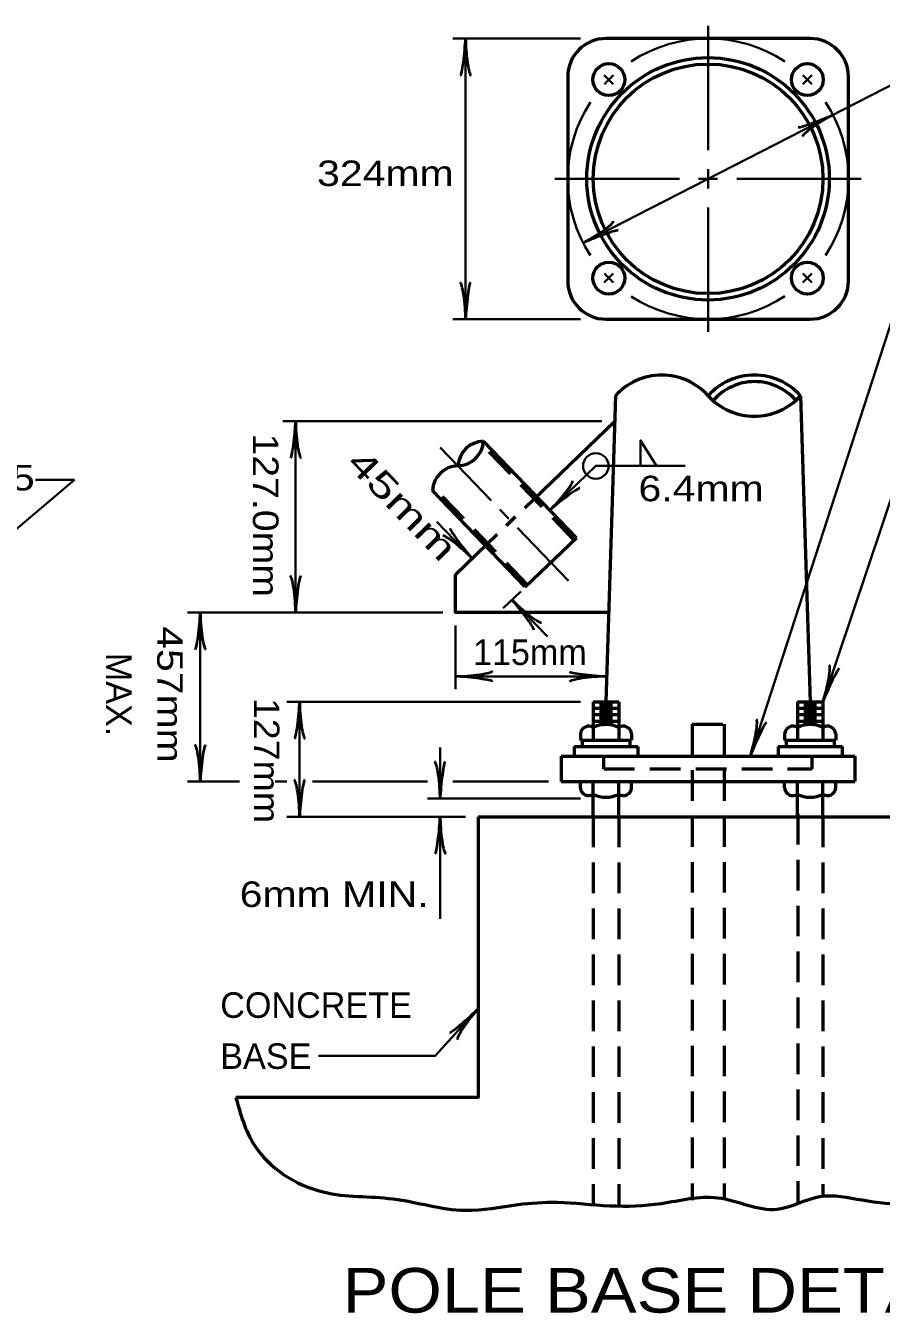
# Model space of a CAD drawing. Extents: x -35 to 821, y -13 to 531.
# Drawn here: x 258.8 to 339.2, y 119.8 to 240.9 of the extents above; entities that cross this region are included whole.
import ezdxf
from ezdxf.enums import TextEntityAlignment as Align

# ---------------------------------------------------------------- set-up
doc = ezdxf.new("R2010")
doc.units = 0
doc.header["$LTSCALE"] = 0.96
doc.linetypes.add('MEDIUM_DASHED', pattern=[4.5, 3, -1.5])
doc.layers.add('1', color=7, linetype='Continuous', lineweight=53)

msp = doc.modelspace()

# ---------------------------------------------------------------- linework, layer by layer
at = {"layer": '1', "lineweight": 35}
for p, q in [((322.9347, 240.8878), (322.9347, 229.1878)), ((310.9347, 239.6878), (298.9347, 239.6878)), ((300.1347, 239.6878), (300.1347, 213.2878)), ((342.1524, 236.3488), (311.1905, 220.4616)), ((313.1766, 236.2458), (314.025, 235.3974)), ((332.6927, 236.2458), (331.8443, 235.3974)), ((308.5347, 226.4878), (320.2347, 226.4878)), ((325.6347, 226.4878), (337.3347, 226.4878)), ((322.9347, 223.7878), (322.9347, 212.0878)), ((314.0251, 217.5782), (313.1767, 216.7298)), ((331.8442, 217.5782), (332.6927, 216.7298)), ((310.9347, 213.2878), (298.9347, 213.2878)), ((333.7347, 177.2878), (343.3335, 205.9941)), ((312.9597, 203.6887), (282.9597, 203.6887)), ((284.1597, 203.6887), (284.1597, 185.6837)), ((299.4156, 199.4884), (297.751, 201.2173)), ((302.5365, 196.2466), (299.4155, 199.4884)), ((225.8081, 166.5182), (263.3752, 198.1859)), ((259.6859, 198.1859), (263.3752, 198.1859)), ((304.2011, 194.5177), (303.3688, 195.3822)), ((300.7525, 190.7812), (297.4234, 194.239)), ((309.8189, 188.6825), (305.0333, 193.6532)), ((303.6759, 186.0998), (305.3196, 187.6823)), ((307.8269, 183.4332), (304.4978, 186.8911)), ((297.997, 185.6837), (273.997, 185.6837)), ((275.197, 185.6837), (275.197, 169.7878)), ((299.197, 184.4837), (299.197, 178.4837)), ((299.197, 179.6837), (313.372, 179.6837)), ((310.9347, 177.2878), (283.3347, 177.2878)), ((284.5347, 177.2878), (284.5347, 166.4878)), ((297.7458, 168.1914), (297.7458, 172.9914)), ((278.8687, 169.7878), (273.997, 169.7878)), ((283.3347, 169.7878), (282.2422, 169.7878)), ((296.5458, 169.7878), (285.7347, 169.7878)), ((307.9347, 169.7878), (298.9458, 169.7878)), ((310.9458, 168.1914), (296.5458, 168.1914)), ((300.1347, 166.4878), (283.3347, 166.4878)), ((297.7458, 166.4878), (297.7458, 156.8878))]:
    msp.add_line(p, q, dxfattribs=at)
at = {"layer": '1'}
for p, q in [((332.5347, 239.6878), (313.3347, 239.6878)), ((309.7347, 236.0878), (309.7347, 216.8878)), ((336.1347, 216.8878), (336.1347, 236.0878)), ((313.3347, 213.2878), (332.5347, 213.2878)), ((314.2347, 206.0878), (313.3346, 177.2878)), ((331.6347, 206.0878), (332.5347, 177.2878)), ((305.7058, 195.5498), (314.1597, 203.6887)), ((310.5569, 192.7245), (301.8181, 201.8014)), ((305.7518, 188.0984), (297.0128, 197.1752)), ((303.9769, 193.8854), (304.8414, 194.7176)), ((299.197, 189.2837), (303.1124, 193.0531)), ((305.7518, 188.0984), (310.5569, 192.7245)), ((312.1347, 177.2878), (314.5347, 177.2878)), ((312.1347, 177.2878), (312.1347, 174.8878)), ((312.7347, 176.9878), (313.9347, 176.9878)), ((314.5347, 177.2878), (314.5347, 174.8878)), ((331.3347, 177.2878), (333.7347, 177.2878)), ((331.3347, 177.2878), (331.3347, 174.8878)), ((331.9347, 176.9878), (333.1347, 176.9878)), ((333.7347, 177.2878), (333.7347, 174.8878)), ((312.1347, 176.6878), (314.5347, 176.6878)), ((312.1347, 176.0878), (314.5347, 176.0878)), ((312.7347, 176.3878), (313.9347, 176.3878)), ((312.7347, 175.7878), (313.9347, 175.7878)), ((331.3347, 176.6878), (333.7347, 176.6878)), ((331.3347, 176.0878), (333.7347, 176.0878)), ((331.9347, 176.3878), (333.1347, 176.3878)), ((331.9347, 175.7878), (333.1347, 175.7878)), ((312.1347, 175.4878), (314.5347, 175.4878)), ((312.1347, 174.8878), (312.1347, 173.6878)), ((312.7347, 175.1878), (313.9347, 175.1878)), ((314.5347, 174.8878), (314.5347, 173.6878)), ((331.3347, 175.4878), (333.7347, 175.4878)), ((331.3347, 174.8878), (331.3347, 173.6878)), ((331.9347, 175.1878), (333.1347, 175.1878)), ((333.7347, 174.8878), (333.7347, 173.6878)), ((310.9347, 174.2878), (310.9347, 173.6878)), ((310.9347, 173.6878), (315.7347, 173.6878)), ((311.0847, 173.6878), (311.0847, 173.0878)), ((315.5847, 173.6878), (315.5847, 173.0878)), ((315.7347, 174.2878), (315.7347, 173.6878)), ((330.1347, 174.2878), (330.1347, 173.6878)), ((330.1347, 173.6878), (334.9347, 173.6878)), ((330.2847, 173.6878), (330.2847, 173.0878)), ((334.7847, 173.6878), (334.7847, 173.0878)), ((334.9347, 174.2878), (334.9347, 173.6878)), ((309.1347, 172.1878), (336.7347, 172.1878)), ((309.1347, 172.1878), (309.1347, 169.7878)), ((310.3347, 173.0878), (316.3347, 173.0878)), ((310.3347, 173.0878), (310.3347, 172.1878)), ((316.3347, 173.0878), (316.3347, 172.1878)), ((329.5347, 173.0878), (335.5347, 173.0878)), ((329.5347, 173.0878), (329.5347, 172.1878)), ((335.5347, 173.0878), (335.5347, 172.1878)), ((336.7347, 172.1878), (336.7347, 169.7878)), ((309.1347, 169.7878), (336.7347, 169.7878)), ((310.9347, 169.1878), (310.9347, 169.7878)), ((312.1347, 166.4878), (312.1347, 169.7878)), ((314.5347, 166.4878), (314.5347, 169.7878)), ((315.7347, 169.1878), (315.7347, 169.7878)), ((330.1347, 169.1878), (330.1347, 169.7878)), ((331.3347, 166.4878), (331.3347, 169.7878)), ((333.7347, 166.4878), (333.7347, 169.7878)), ((334.9347, 169.1878), (334.9347, 169.7878))]:
    msp.add_line(p, q, dxfattribs=at)
at = {"layer": '1', "linetype": 'MEDIUM_DASHED'}
for p, q in [((310.3406, 192.5162), (301.7641, 201.4245)), ((305.9678, 188.3064), (297.0667, 197.5516)), ((321.4347, 175.1878), (321.4347, 130.4043)), ((321.4347, 175.1878), (324.4347, 175.1878)), ((324.4347, 175.1878), (324.4347, 130.6498)), ((313.1378, 170.9878), (313.1378, 172.1878)), ((332.7316, 170.9878), (332.7316, 172.1878)), ((313.1378, 170.9878), (332.7316, 170.9878)), ((312.1347, 166.4878), (312.1347, 129.973)), ((314.5347, 166.4878), (314.5347, 129.913)), ((331.359, 166.7575), (331.359, 130.1869)), ((333.7347, 166.4878), (333.7347, 130.7353))]:
    msp.add_line(p, q, dxfattribs=at)
at = {"layer": '1', "lineweight": 35}
for points in [[(322.0347, 226.4878), (322.9347, 226.4878), (323.8347, 226.4878)], [(322.9347, 227.3878), (322.9347, 226.4878), (322.9347, 225.5878)], [(326.909, 172.1878), (342.9245, 221.5527), (344.2093, 221.5527)], [(316.5825, 199.4791), (316.5825, 201.8791), (318.0825, 199.4791)], [(308.0602, 195.3178), (312.3825, 199.4791), (320.7825, 199.4791)], [(301.3347, 148.4451), (297.2801, 143.9966), (286.2943, 143.9966)]]:
    msp.add_lwpolyline(points, dxfattribs=at)
at = {"layer": '1'}
for points in [[(313.597, 185.6837), (299.197, 185.6837), (299.197, 189.2837)], [(301.3347, 166.4878), (301.3347, 140.0878), (278.5347, 140.0878)], [(301.3347, 166.4878), (344.5347, 166.4878), (344.5347, 130.4878)]]:
    msp.add_lwpolyline(points, dxfattribs=at)
for centre, radius in [((322.9347, 226.4878), 11.4), ((313.6009, 235.8216), 1.5), ((322.9347, 226.4878), 10.8), ((332.2685, 235.8216), 1.5), ((313.6009, 217.154), 1.5), ((332.2685, 217.154), 1.5)]:
    msp.add_circle(centre, radius, dxfattribs=at)
at = {"layer": '1', "lineweight": 35}
msp.add_circle((312.3825, 199.4791), 1.2, dxfattribs=at)
at = {"layer": '1'}
for centre, radius, start, end in [((313.3347, 236.0878), 3.6, 90, 180), ((332.5347, 236.0878), 3.6, 0, 90), ((313.3347, 216.8878), 3.6, 180, 270), ((332.5347, 216.8878), 3.6, 270, 0), ((318.5847, 202.1523), 5.8661, 42.13622, 137.86423), ((327.2847, 202.1523), 5.8661, 42.13622, 137.86378), ((327.3185, 202.2532), 5.1594, 41.23283, 139.26556), ((327.2847, 210.0233), 5.8661, 222.13622, 317.86378), ((301.8862, 199.3265), 2.476, 91.57437, 176.25114), ((299.3475, 201.9635), 2.476, 271.57437, 356.25114), ((299.4835, 197.0133), 2.476, 91.57437, 176.25114), ((311.7162, 174.2249), 0.784, 57.73362, 175.39648), ((313.3347, 172.3871), 2.7738, 64.36559, 115.6344), ((314.9532, 174.2249), 0.784, 4.60352, 122.26638), ((330.9162, 174.2249), 0.784, 57.73362, 175.39648), ((332.5347, 172.3871), 2.7738, 64.36559, 115.6344), ((334.1532, 174.2249), 0.784, 4.60352, 122.26638), ((311.7162, 169.2507), 0.784, 184.60352, 302.26638), ((313.3347, 171.0885), 2.7738, 244.3656, 295.63441), ((314.9532, 169.2507), 0.784, 237.73362, 355.39648), ((330.9162, 169.2507), 0.784, 184.60352, 302.26638), ((332.5347, 171.0885), 2.7738, 244.3656, 295.63441), ((334.1532, 169.2507), 0.784, 237.73362, 355.39648)]:
    msp.add_arc(centre, radius, start, end, dxfattribs=at)
at = {"layer": '1', "lineweight": 35}
for start, end in [(56.77694, 123.15721), (132.39545, 137.60578), (42.39484, 47.60516), (146.85345, 213.14435), (326.86294, 33.16035), (222.39484, 227.60516), (312.39437, 317.6047), (236.86662, 303.17329)]:
    msp.add_arc((322.9347, 226.4878), 13.2, start, end, dxfattribs=at)
at = {"layer": '1', "lineweight": 40}
for centre, major_axis, ratio, start_param, end_param in [((299.8808, 238.3432), (0.2108, 2.1077), 0.07063, 3.14071475, 5.41810995), ((299.8808, 238.3432), (0.2108, 2.1077), 0.07063, 3.14071475, 5.41810995), ((300.4663, 238.3784), (-0.1874, 2.1428), 0.122415, 0.89635335, 3.14159265), ((300.4663, 238.3784), (-0.1874, 2.1428), 0.122415, 0.89635335, 3.14159265), ((333.3667, 232.1261), (1.9715, 0.7747), 0.07063, 3.14071475, 5.41810995), ((333.3667, 232.1261), (1.9715, 0.7747), 0.07063, 3.14071475, 5.41810995), ((333.6652, 231.6212), (1.821, 1.145), 0.122415, 0.89635335, 3.14159265), ((333.6652, 231.6212), (1.821, 1.145), 0.122415, 0.89635335, 3.14159265), ((312.2042, 221.3544), (-1.821, -1.145), 0.122415, 0.89635335, 3.14159265), ((312.5027, 220.8495), (-1.9715, -0.7747), 0.07063, 3.14071475, 5.41810995), ((299.8031, 214.5972), (0.1874, -2.1428), 0.122415, 0.89635335, 3.14159265), ((300.3886, 214.6324), (-0.2108, -2.1077), 0.07063, 3.14071475, 5.41810995), ((283.9058, 202.3441), (0.2108, 2.1077), 0.07063, 3.14071475, 5.41810995), ((283.9058, 202.3441), (0.2108, 2.1077), 0.07063, 3.14071475, 5.41810995), ((284.4913, 202.3793), (-0.1874, 2.1428), 0.122415, 0.89635335, 3.14159265), ((284.4913, 202.3793), (-0.1874, 2.1428), 0.122415, 0.89635335, 3.14159265), ((308.7736, 196.4648), (-1.4137, -1.6212), 0.122415, 0.89635335, 3.14159265), ((309.205, 196.0674), (-1.6646, -1.31), 0.07063, 3.14071475, 5.41810995), ((299.6055, 191.4945), (1.6212, -1.4137), 0.122415, 0.89635335, 3.14159265), ((299.6055, 191.4945), (1.6212, -1.4137), 0.122415, 0.89635335, 3.14159265), ((300.0028, 191.9259), (-1.31, 1.6646), 0.07063, 6.28230741, 8.55970261), ((300.0028, 191.9259), (-1.31, 1.6646), 0.07063, 6.28230741, 8.55970261), ((283.8281, 186.9931), (0.1874, -2.1428), 0.122415, 0.89635335, 3.14159265), ((284.4136, 187.0283), (-0.2108, -2.1077), 0.07063, 3.14071475, 5.41810995), ((305.2474, 185.7463), (1.31, -1.6646), 0.07063, 6.28230741, 8.55970261), ((305.6448, 186.1777), (-1.6212, 1.4137), 0.122415, 0.89635335, 3.14159265), ((274.9431, 184.3391), (0.2108, 2.1077), 0.07063, 3.14071475, 5.41810995), ((274.9431, 184.3391), (0.2108, 2.1077), 0.07063, 3.14071475, 5.41810995), ((275.5286, 184.3743), (-0.1874, 2.1428), 0.122415, 0.89635335, 3.14159265), ((275.5286, 184.3743), (-0.1874, 2.1428), 0.122415, 0.89635335, 3.14159265), ((333.8355, 178.6348), (-0.5018, -2.0917), 0.122415, 0.89635335, 3.14159265), ((333.8355, 178.6348), (-0.5018, -2.0917), 0.122415, 0.89635335, 3.14159265), ((300.5416, 179.4298), (-2.1077, 0.2108), 0.07063, 3.14071475, 5.41810995), ((300.5416, 179.4298), (-2.1077, 0.2108), 0.07063, 3.14071475, 5.41810995), ((300.5064, 180.0153), (-2.1428, -0.1874), 0.122415, 0.89635335, 3.14159265), ((300.5064, 180.0153), (-2.1428, -0.1874), 0.122415, 0.89635335, 3.14159265), ((312.0626, 179.3521), (2.1428, 0.1874), 0.122415, 0.89635335, 3.14159265), ((312.0274, 179.9376), (2.1077, -0.2108), 0.07063, 3.14071475, 5.41810995), ((334.4019, 178.4825), (-0.8683, -1.9321), 0.07063, 3.14071475, 5.41810995), ((334.4019, 178.4825), (-0.8683, -1.9321), 0.07063, 3.14071475, 5.41810995), ((284.2808, 175.9432), (0.2108, 2.1077), 0.07063, 3.14071475, 5.41810995), ((284.2808, 175.9432), (0.2108, 2.1077), 0.07063, 3.14071475, 5.41810995), ((284.8663, 175.9784), (-0.1874, 2.1428), 0.122415, 0.89635335, 3.14159265), ((284.8663, 175.9784), (-0.1874, 2.1428), 0.122415, 0.89635335, 3.14159265), ((326.9977, 173.5356), (-0.483, -2.0961), 0.122415, 0.89635335, 3.14159265), ((327.5655, 173.3884), (-0.8509, -1.9398), 0.07063, 3.14071475, 5.41810995), ((274.8654, 171.0972), (0.1874, -2.1428), 0.122415, 0.89635335, 3.14159265), ((275.4509, 171.1324), (-0.2108, -2.1077), 0.07063, 3.14071475, 5.41810995), ((297.4142, 169.5008), (0.1874, -2.1428), 0.122415, 0.89635335, 3.14159265), ((297.4142, 169.5008), (0.1874, -2.1428), 0.122415, 0.89635335, 3.14159265), ((297.9997, 169.536), (-0.2108, -2.1077), 0.07063, 3.14071475, 5.41810995), ((297.9997, 169.536), (-0.2108, -2.1077), 0.07063, 3.14071475, 5.41810995), ((284.2031, 167.7972), (0.1874, -2.1428), 0.122415, 0.89635335, 3.14159265), ((284.7886, 167.8324), (-0.2108, -2.1077), 0.07063, 3.14071475, 5.41810995), ((297.4919, 165.1432), (0.2108, 2.1077), 0.07063, 3.14071475, 5.41810995), ((298.0774, 165.1784), (-0.1874, 2.1428), 0.122415, 0.89635335, 3.14159265), ((300.2413, 147.6224), (-1.5756, -1.4158), 0.07063, 6.28230741, 8.55970261), ((300.6977, 147.254), (1.305, 1.7099), 0.122415, 0.89635335, 3.14159265)]:
    msp.add_ellipse(centre, major_axis=major_axis, ratio=ratio, start_param=start_param, end_param=end_param, dxfattribs=at)
at = {"layer": '1'}
msp.add_spline([(278.5347, 140.0878), (280.2678, 135.6135), (286.7374, 131.1911), (293.3149, 130.544), (300.108, 129.4653), (305.0681, 130.0046), (308.7343, 130.2204), (313.6943, 129.8968), (318.5466, 130.1125), (323.8301, 130.6518), (329.4372, 129.5732), (333.4268, 130.7597), (337.4164, 130.4361), (341.7295, 130.1125), (344.5347, 130.4878)], degree=3, dxfattribs=at)

# ---------------------------------------------------------------- texts
for s, height, width, p in [('324mm', 2.4, 1.2, (286.1756, 225.8104)), ('127.0mm SCH. 40 PIPE-DN125', 2.4, 1.25, (202.5537, 197.1753)), ('6.4mm', 2.4, 1.2, (316.3928, 196.1635)), ('6mm MIN.', 2.4, 1.2, (278.9018, 158.0001)), ('POLE BASE DETAIL', 4.2, 1.15, (288.5785, 119.8421))]:
    msp.add_text(s, height=height, dxfattribs=dict(at, width=width)).set_placement(p)
for s, rotation, width, p in [('127.0mm', 270, 1.15, (280.1468, 202.5408)), ('45mm', 313.914, 1.45, (288.8461, 199.6282)), ('127mm', 270, 1.1, (280.2366, 177.659))]:
    msp.add_text(s, height=2.4, rotation=rotation, dxfattribs=dict(at, width=width)).set_placement(p)
at = {"layer": '1', "width": 1.2}
msp.add_text('457mm', height=2.4, rotation=270, dxfattribs=at).set_placement((271.142, 177.9831), align=Align.CENTER)
at = {"layer": '1'}
for s, p in [('115mm', (300.8278, 180.7623)), ('CONCRETE', (277.0719, 147.5671)), ('BASE', (277.0719, 142.7671))]:
    msp.add_text(s, height=2.4, dxfattribs=at).set_placement(p)
msp.add_text('MAX.', height=2.4, rotation=270, dxfattribs=at).set_placement((266.342, 177.9831), align=Align.CENTER)

doc.saveas('drawing.dxf')
